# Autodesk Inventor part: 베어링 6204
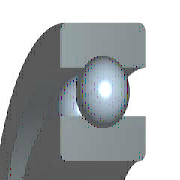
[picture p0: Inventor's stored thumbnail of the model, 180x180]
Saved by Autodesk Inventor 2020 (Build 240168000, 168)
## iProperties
IsCustomPart: 0
Created: 2015-12
Part Number: 베어링 6204
Material: 강철, 연강
Description: 깊은 그루브 볼 베어링
Document SubType Name: Modeling
Standard: KS B 2023
Designer: mdu
Standards Organization: KS
Language: ko-KR
Size Designation: 6204 - 20 x 47 x 14
Categories: <MemberInstance><Categories><Category DisplayName="샤프트 부품" InternalName="7f7aeb1f-a693-4053-b835-cee3144e0d98" Mnemonic="SHFT"><Category DisplayName="베어링" Inter
Density: 7.86 g/cm^3
Mass: 104.255 g
Surface Area: 87.8912 cm^2
Volume: 13.264 cm^3
Appearance: 강철
Author: mud
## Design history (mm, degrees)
sketch "스케치" dims "d0" = 7.02 (= -0.26 x WD + 0.26 x BD)
  geometry: L1 (3.49, 16.75)-(10.51, 16.75); L2 (7, 16.75)-(7, 13.24); L3 (7, 16.75)-(7, 20.26); L4 (4.392, 14.401)-(0, 14.401); L5 (0, 10)-(14, 10); L6 (4.392, 19.099)-(0, 19.099); L7 (0, 23.5)-(14, 23.5); L8 (14, 10)-(14, 14.401); L9 (9.608, 14.401)-(14, 14.401); L10 (9.608, 19.099)-(14, 19.099); L11 (14, 23.5)-(14, 19.099); L12 (-1.4, 0)-(8.4, 0) reference; L13 (0, -0.3)-(0, 5.3) reference
  constraints: 22 end point, 4 point on line, 2 collinear, 2 perpendicular, 2 symmetric about line, 1 midpoint, 1 parallel, 14 other
  dimensions: "d9" = 20 diameter of L5 L12 (= WD); "d11" = 47 diameter of L7 L12 (= BD); "d12" = 14 distance between parallel lines of L8 L13 (= KB); "d13" = 28.802 diameter of L9 L12 (= 0.326 x BD + 0.674 x WD)
revolve "본체" stored, may be unused: angle "d6" = 90 deg
revolve "볼" stored, may be unused: angle "d7" = 90 deg
pattern_circular "IDS_ARRAYBALL[SIMPL:T]" dims angle "d3" = 360 deg
body "Solid1"
fillet "모깎기1" dims "d1" = 1 (= KRS)
other parameters: "WD" = 20 [user parameter; used in 5 equation terms], "BD" = 47 [user parameter; used in 5 equation terms], "KB" = 14 [user parameter; used in 1 equation term], "KRS" = 1 [user parameter; used in 1 equation term], "d4" = 0, "d5" = 0, "d8" = 0, "d14" = 0, "d15" = 0, "BBA" = 0 [user parameter], "BC0" = 6550000 [user parameter], "BC" = 1.27e+07 [user parameter], "BR" = 23.5 (= 0.5 x BD) [user parameter]
